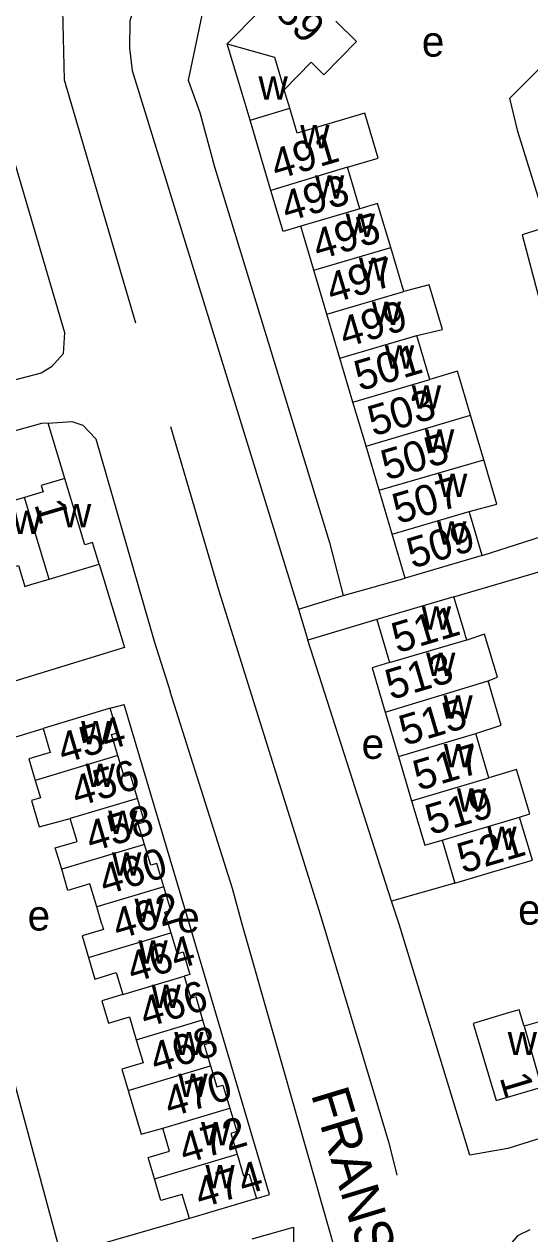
# Model space of a CAD drawing. Extents: x 157768 to 159790, y 387230 to 389604.
# Drawn here: x 158428.3 to 158494.9, y 388459.2 to 388618.6 of the extents above; entities that cross this region are included whole.
import ezdxf

# ---------------------------------------------------------------- set-up
doc = ezdxf.new("R2010")
doc.units = 0
for name, color, linetype in [('BLT_Basislijn', 7, 'Continuous'), ('BLT_Bebouwing', 7, 'Continuous'), ('BLT_Centroide', 7, 'Continuous'), ('BLT_Huisnummer', 7, 'Continuous'), ('BLT_Huisnummer_ tussenligend', 7, 'Continuous'), ('BLT_Onderverdeling_panden', 7, 'Continuous'), ('BLT_Straatnaam', 7, 'Continuous')]:
    doc.layers.add(name, color=color, linetype=linetype)

msp = doc.modelspace()

# ---------------------------------------------------------------- linework, layer by layer
at = {"layer": 'BLT_Basislijn'}
for p, q in [((158433.68, 388558.7), (158431.49, 388566.01)), ((158438.19, 388547.4), (158441.55, 388536.43)), ((158470.33, 388543.29), (158478.52, 388545.55)), ((158464.47, 388541.48), (158470.33, 388543.29)), ((158464.47, 388541.48), (158465.69, 388537.39)), ((158474.79, 388540.11), (158465.69, 388537.39)), ((158441.55, 388536.43), (158415.33, 388528.43)), ((158445.45, 388537.29), (158447.56, 388530.62)), ((158476.72, 388503), (158465.69, 388537.39)), ((158439.65, 388528.43), (158441.5, 388528.94)), ((158485.08, 388505.4), (158476.72, 388503))]:
    msp.add_line(p, q, dxfattribs=at)
for points in [[(158540.2, 388736.5), (158441.06, 388636.74), (158435.4, 388628.23), (158433.34, 388620.46), (158433.58, 388611.25), (158443, 388579.2)], [(158495.96, 388677.3), (158495.15, 388676.49), (158446.52, 388626.96), (158443.38, 388622.54), (158442.23, 388619), (158442.2, 388615.42), (158442.54, 388612.47), (158464.47, 388541.48)], [(158500.65, 388672.69), (158452.78, 388624.82), (158449.94, 388611.17), (158451.45, 388606.91), (158453.4, 388599.78), (158468.54, 388550.25), (158470.33, 388543.29)], [(158423.34, 388624.24), (158422.85, 388621.26), (158422.88, 388615.39), (158423.16, 388613.37), (158433.63, 388577.92), (158433.44, 388575.14), (158431.93, 388573.41), (158430.54, 388572.56), (158415.04, 388568.52), (158407.87, 388566.42), (158398.7, 388563.8)], [(158497.26, 388591.88), (158493.37, 388604.42), (158492.33, 388608.83), (158503.91, 388620.45)], [(158497.26, 388591.88), (158493.92, 388590.79), (158496.26, 388582.03), (158503.22, 388560.4), (158503.93, 388556.93)], [(158431.49, 388566.01), (158430.57, 388565.95), (158405.12, 388558.84)], [(158431.49, 388566.01), (158434.58, 388566.22), (158436.02, 388565.72), (158437.77, 388563.91), (158445.45, 388537.29)], [(158447.61, 388565.57), (158453.98, 388543.88), (158467.36, 388501.13), (158476.37, 388471.15), (158477.42, 388466.89)], [(158488.66, 388548.57), (158504.43, 388553.61), (158503.93, 388556.93)], [(158484.95, 388543.13), (158504.22, 388548.79), (158514.71, 388514.81)], [(158469.1, 388457.64), (158457.04, 388500), (158455.76, 388504.68), (158447.56, 388530.62)], [(158458.93, 388463.84), (158460.66, 388464.37), (158450.11, 388500), (158441.5, 388528.94)], [(158450.08, 388461.19), (158433.2, 388456.33), (158421.37, 388500), (158415.41, 388521.08), (158430.8, 388525.78)], [(158524.29, 388483.84), (158523.96, 388483.55), (158519.38, 388480.35), (158510.33, 388476.12), (158492.03, 388470.43), (158487.03, 388469.56), (158477.71, 388500), (158476.72, 388503)], [(158458.35, 388458.52), (158463.79, 388460.06), (158463.84, 388448.5), (158471.85, 388416.98), (158482.41, 388385.75), (158482.77, 388383.92), (158482.68, 388382.46), (158482.13, 388381.09), (158480.77, 388380.09), (158470.09, 388376.35)], [(158494.95, 388459.72), (158493.32, 388458.93), (158491.63, 388456.91), (158491.14, 388456.07), (158490.98, 388453.03), (158498.88, 388422.81), (158509.82, 388389.8), (158515.39, 388376.01)]]:
    msp.add_lwpolyline(points, dxfattribs=at)
at = {"layer": 'BLT_Bebouwing'}
for p, q in [((158460.82, 388596.66), (158458.07, 388605.92)), ((158472.55, 388594.25), (158470.92, 388599.73)), ((158462.42, 388591.24), (158460.82, 388596.66)), ((158464.75, 388591.93), (158462.42, 388591.24)), ((158466.47, 388586.14), (158464.75, 388591.93)), ((158478.33, 388583.35), (158476.61, 388589.15)), ((158468.19, 388580.34), (158466.47, 388586.14)), ((158469.92, 388574.54), (158468.19, 388580.34)), ((158481.78, 388571.76), (158480.06, 388577.55)), ((158471.64, 388568.74), (158469.92, 388574.54)), ((158485.43, 388572.84), (158481.78, 388571.76)), ((158473.36, 388562.95), (158471.64, 388568.74)), ((158475.08, 388557.15), (158473.36, 388562.95)), ((158476.8, 388551.35), (158475.08, 388557.15)), ((158478.52, 388545.55), (158476.8, 388551.35)), ((158488.66, 388548.57), (158478.52, 388545.55)), ((158484.95, 388543.13), (158474.79, 388540.11)), ((158474.79, 388540.11), (158476.47, 388534.45)), ((158439.65, 388528.43), (158430.8, 388525.78)), ((158475.9, 388527.92), (158477.64, 388522.07)), ((158489.54, 388519.25), (158487.81, 388525.09)), ((158477.64, 388522.07), (158479.37, 388516.23)), ((158495.28, 388508.43), (158493.6, 388514.09)), ((158483.4, 388511.07), (158485.08, 388505.4)), ((158438.55, 388500), (158437.87, 388502.25)), ((158447.3, 388500), (158447.65, 388498.84)), ((158499.22, 388488.01), (158494.21, 388486.52)), ((158458.93, 388463.84), (158450.08, 388461.19))]:
    msp.add_line(p, q, dxfattribs=at)
for points in [[(158455.08, 388615.98), (158459.34, 388620.27)], [(158466.13, 388613.54), (158467.79, 388611.9), (158472.1, 388616.27), (158469.37, 388618.96)], [(158457.02, 388609.42), (158455.08, 388615.98)], [(158462.57, 388609.93), (158466.13, 388613.54)], [(158463.3, 388607.48), (158462.57, 388609.93)], [(158458.07, 388605.92), (158457.02, 388609.42)], [(158464.27, 388604.21), (158463.3, 388607.48)], [(158470.92, 388599.73), (158474.95, 388600.93), (158473.19, 388606.86), (158464.27, 388604.21)], [(158476.61, 388589.15), (158474.89, 388594.94), (158472.55, 388594.25)], [(158480.06, 388577.55), (158483.45, 388578.35), (158481.69, 388584.23), (158478.33, 388583.35)], [(158487.15, 388567.04), (158485.43, 388572.84)], [(158488.89, 388561.18), (158487.15, 388567.04)], [(158486.94, 388554.36), (158490.62, 388555.34), (158488.89, 388561.18)], [(158433.68, 388558.7), (158430.54, 388557.77), (158430.79, 388556.93), (158428.36, 388556.21)], [(158438.19, 388547.4), (158437.33, 388550.27), (158436.29, 388549.96), (158433.68, 388558.7)], [(158428.36, 388556.21), (158425.2, 388555.26), (158424.95, 388556.08), (158421.92, 388555.17)], [(158488.66, 388548.57), (158487.24, 388553.36), (158486.94, 388554.36)], [(158431.58, 388545.44), (158438.19, 388547.4)], [(158424.55, 388546.36), (158427.55, 388547.26), (158428.38, 388544.48), (158429.18, 388544.72), (158431.58, 388545.44)], [(158486.63, 388537.46), (158486.44, 388538.11), (158486.37, 388538.33), (158484.95, 388543.13)], [(158489.46, 388532.04), (158490.67, 388532.52), (158488.98, 388538.2), (158486.64, 388537.41), (158486.63, 388537.46)], [(158476.47, 388534.45), (158474.17, 388533.76), (158475.9, 388527.92)], [(158487.81, 388525.09), (158491.19, 388526.22), (158489.46, 388532.04)], [(158440.66, 388522.19), (158439.83, 388524.95), (158440.62, 388525.18), (158439.65, 388528.43)], [(158430.8, 388525.78), (158431.75, 388522.59), (158428.93, 388521.75), (158429.77, 388518.93)], [(158443.23, 388516.56), (158442.3, 388519.67), (158441.48, 388519.43), (158440.66, 388522.19)], [(158493.6, 388514.09), (158494.94, 388514.5), (158493.2, 388520.38), (158489.54, 388519.25)], [(158429.77, 388518.93), (158430.46, 388516.63), (158429.26, 388516.27), (158430.3, 388512.8), (158434.37, 388513.92)], [(158444.17, 388510.47), (158443.35, 388513.21), (158444.16, 388513.46), (158443.23, 388516.56)], [(158479.37, 388516.23), (158481.11, 388510.38), (158483.4, 388511.07)], [(158433.25, 388507.21), (158432.4, 388510.03), (158435.28, 388510.89), (158434.37, 388513.92)], [(158446.7, 388504.89), (158445.78, 388507.97), (158444.99, 388507.74), (158444.17, 388510.47)], [(158485.08, 388505.4), (158489.88, 388506.82), (158495.28, 388508.43)], [(158437.87, 388502.25), (158436.97, 388505.29), (158434.08, 388504.42), (158433.25, 388507.21)], [(158447.3, 388500), (158446.83, 388501.57), (158447.62, 388501.81), (158446.7, 388504.89)], [(158438.55, 388500), (158438.76, 388499.29), (158435.93, 388498.44), (158436.78, 388495.59)], [(158447.65, 388498.84), (158448.47, 388496.09), (158449.26, 388496.33), (158450.15, 388493.35), (158449.4, 388493.13)], [(158436.78, 388495.59), (158437.63, 388492.74), (158440.45, 388493.59), (158441.31, 388490.71)], [(158449.4, 388493.13), (158450.27, 388490.24), (158450.91, 388490.43), (158451.82, 388487.36)], [(158441.31, 388490.71), (158438.55, 388489.88), (158439.43, 388486.95), (158442.18, 388487.77), (158443.08, 388484.74)], [(158494.21, 388486.52), (158493.56, 388488.71), (158492.26, 388488.32), (158487.47, 388486.89), (158490.5, 388476.74), (158496.34, 388478.48)], [(158451.82, 388487.36), (158452.75, 388484.27), (158452.05, 388484.1), (158452.88, 388481.32)], [(158443.08, 388484.74), (158443.99, 388481.72), (158441.17, 388480.88), (158442.01, 388478.07)], [(158452.88, 388481.32), (158453.72, 388478.53), (158454.51, 388478.77), (158455.42, 388475.73)], [(158442.01, 388478.07), (158443.73, 388472.29), (158446.56, 388473.08)], [(158455.42, 388475.73), (158456.34, 388472.65), (158455.54, 388472.41), (158456.36, 388469.68)], [(158445.48, 388466.43), (158444.91, 388468.34), (158444.65, 388469.23), (158447.46, 388470.07), (158446.56, 388473.08)], [(158456.36, 388469.68), (158457.21, 388466.81), (158457.98, 388467.04), (158458.93, 388463.84)], [(158450.08, 388461.19), (158449.13, 388464.38), (158446.34, 388463.55), (158445.48, 388466.43)]]:
    msp.add_lwpolyline(points, dxfattribs=at)
at = {"layer": 'BLT_Onderverdeling_panden'}
for p, q in [((158458.07, 388605.92), (158463.3, 388607.48)), ((158470.92, 388599.73), (158460.82, 388596.66)), ((158472.55, 388594.25), (158464.75, 388591.93)), ((158466.47, 388586.14), (158476.61, 388589.15)), ((158468.19, 388580.34), (158478.33, 388583.35)), ((158469.92, 388574.54), (158480.06, 388577.55)), ((158471.64, 388568.74), (158481.78, 388571.76)), ((158473.36, 388562.95), (158487.15, 388567.04)), ((158475.08, 388557.15), (158488.89, 388561.18)), ((158431.58, 388545.44), (158428.36, 388556.21)), ((158476.8, 388551.35), (158486.94, 388554.36)), ((158476.47, 388534.45), (158486.63, 388537.46)), ((158475.9, 388527.92), (158489.46, 388532.04)), ((158477.64, 388522.07), (158487.81, 388525.09)), ((158440.66, 388522.19), (158429.77, 388518.93)), ((158479.37, 388516.23), (158489.54, 388519.25)), ((158443.23, 388516.56), (158434.37, 388513.92)), ((158483.4, 388511.07), (158493.6, 388514.09)), ((158444.17, 388510.47), (158433.25, 388507.21)), ((158446.7, 388504.89), (158437.87, 388502.25)), ((158436.78, 388495.59), (158447.65, 388498.84)), ((158441.31, 388490.71), (158449.4, 388493.13)), ((158443.08, 388484.74), (158451.82, 388487.36)), ((158442.01, 388478.07), (158452.88, 388481.32)), ((158446.56, 388473.08), (158455.42, 388475.73)), ((158445.48, 388466.43), (158456.36, 388469.68))]:
    msp.add_line(p, q, dxfattribs=at)
for points in [[(158455.08, 388615.98), (158461.3, 388614.23), (158462.57, 388609.93)], [(158494.21, 388486.52), (158496.48, 388478.52), (158496.34, 388478.48)]]:
    msp.add_lwpolyline(points, dxfattribs=at)

# ---------------------------------------------------------------- texts
at = {"layer": 'BLT_Centroide'}
for s, p in [('e', (158480.71, 388614.29)), ('w', (158459.19, 388608.61)), ('w', (158464.68, 388602.22)), ('w', (158466.63, 388595.59)), ('w', (158470.68, 388590.53)), ('w', (158472.41, 388584.75)), ('w', (158474.12, 388578.94)), ('w', (158475.84, 388573.16)), ('w', (158479.39, 388567.91)), ('w', (158481.12, 388562.09)), ('w', (158482.84, 388556.28)), ('w', (158433.28, 388552.27)), ('w', (158426.75, 388551.38)), ('w', (158482.73, 388549.97)), ('w', (158480.7, 388538.78)), ('w', (158481.27, 388532.69)), ('w', (158483.55, 388527.06)), ('w', (158435.81, 388523.69)), ('e', (158472.78, 388521.76)), ('w', (158483.59, 388520.66)), ('w', (158436.41, 388518.06)), ('w', (158485.33, 388514.81)), ('w', (158439.37, 388511.88)), ('w', (158489.34, 388509.75)), ('w', (158439.88, 388506.38)), ('w', (158442.85, 388500.25)), ('e', (158493.4, 388499.91)), ('e', (158428.76, 388499.14)), ('e', (158448.48, 388498.89)), ('w', (158443.37, 388494.78)), ('w', (158445.09, 388488.94)), ('w', (158448.08, 388482.72)), ('w', (158492.03, 388482.72)), ('w', (158448.62, 388477.19)), ('w', (158451.62, 388470.84)), ('w', (158452.19, 388465.19))]:
    msp.add_text(s, height=4, dxfattribs=at).set_placement(p)
at = {"layer": 'BLT_Huisnummer'}
for s, rotation, p in [('489', 315.2486, (158459.11, 388622.05)), ('491', 16.5386, (158461.54, 388598.04)), ('495', 16.5386, (158467.04, 388587.46)), ('499', 16.5384, (158470.55, 388575.9)), ('503', 16.5384, (158474.31, 388564.23)), ('1', 286.6252, (158429.61, 388555.31)), ('509', 16.5384, (158479.45, 388546.81)), ('511', 16.5322, (158477.46, 388535.66)), ('515', 16.5322, (158478.43, 388523.46)), ('454', 16.6434, (158433.44, 388521.1)), ('458', 16.6434, (158437.12, 388509.46)), ('521', 16.5324, (158486.1, 388506.63)), ('462', 16.6434, (158440.65, 388497.93)), ('466', 16.6434, (158444.26, 388486.29)), ('470', 16.6434, (158447.48, 388474.5)), ('1', 286.6123, (158490.94, 388479.77)), ('474', 16.6434, (158451.51, 388462.52))]:
    msp.add_text(s, height=4, rotation=rotation, dxfattribs=at).set_placement(p)
at = {"layer": 'BLT_Huisnummer_ tussenligend'}
for s, rotation, p in [('493', 16.5386, (158462.92, 388592.49)), ('497', 16.5384, (158468.84, 388581.73)), ('501', 16.5384, (158472.53, 388570.19)), ('505', 16.5384, (158476.06, 388558.42)), ('507', 16.5384, (158477.56, 388552.68)), ('513', 16.5322, (158476.62, 388529.5)), ('517', 16.5352, (158480.28, 388517.53)), ('456', 16.6434, (158435.24, 388515.41)), ('519', 16.5352, (158481.89, 388511.7)), ('460', 16.6434, (158438.91, 388503.77)), ('464', 16.6434, (158442.58, 388492.23)), ('468', 16.6434, (158445.62, 388480.3)), ('472', 16.6434, (158449.44, 388468.37))]:
    msp.add_text(s, height=4, rotation=rotation, dxfattribs=at).set_placement(p)
at = {"layer": 'BLT_Straatnaam'}
msp.add_text('FRANSEBAAN', height=5, rotation=286.8202, dxfattribs=at).set_placement((158466.07, 388477.58))

doc.saveas('drawing.dxf')
